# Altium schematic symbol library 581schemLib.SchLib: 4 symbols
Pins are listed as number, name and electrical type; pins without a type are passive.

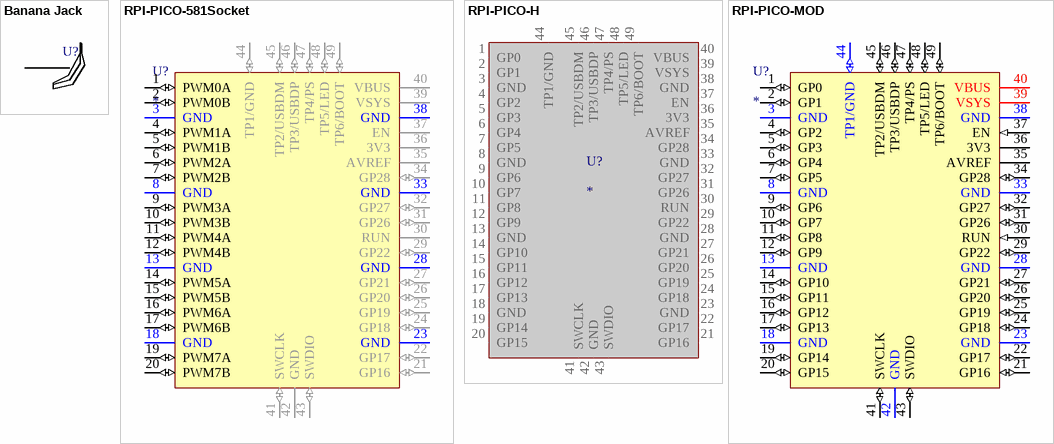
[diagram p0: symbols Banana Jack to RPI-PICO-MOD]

## Banana Jack
designator U?  (value not drawn)
575-8
footprint Banana Jack (575-8)
pins: 1

## RPI-PICO-581Socket
designator U?
RASPBERRY PI PICO RP2040 BOARD; Manufacturer: Raspberry Pi Foundation; Manufacturer Part No: SC0915
footprint RPI-PICO-MOD (RASPBERRY PI PICO RP2040 BOARD)
pins: 1 PWM0A (io), 2 PWM0B (io), 3 GND (power), 4 PWM1A (io), 5 PWM1B (io), 6 PWM2A (io), 7 PWM2B (io), 8 GND (power), 9 PWM3A (io), 10 PWM3B (io), 11 PWM4A (io), 12 PWM4B (io), 13 GND (power), 14 PWM5A (io), 15 PWM5B (io), 16 PWM6A (io), 17 PWM6B (io), 18 GND (power), 19 PWM7A (io), 20 PWM7B (io), 21 GP16 (io), 22 GP17 (io), 23 GND (power), 24 GP18 (io), 25 GP19 (io), 26 GP20 (io), 27 GP21 (io), 28 GND (power), 29 GP22 (io), 30 RUN (hiz), 31 GP26 (io), 32 GP27 (io), 33 GND (power), 34 GP28 (io), 35 AVREF (power), 36 3V3 (power), 37 EN (hiz), 38 GND (power), 39 VSYS (power), 40 VBUS (power), 41 SWCLK (io), 42 GND (power), 43 SWDIO (io), 44 TP1/GND (io), 45 TP2/USBDM (io), 46 TP3/USBDP (io), 47 TP4/PS (io), 48 TP5/LED (io), 49 TP6/BOOT (io)

## RPI-PICO-H
designator U?
RASPBERRY PI PICO HRP2040 BOARD; Manufacturer: Raspberry Pi Foundation; Manufacturer Part No: SC0915
pins: 1 GP0 (hiz), 2 GP1 (hiz), 3 GND (hiz), 4 GP2 (hiz), 5 GP3 (hiz), 6 GP4 (hiz), 7 GP5 (hiz), 8 GND (hiz), 9 GP6 (hiz), 10 GP7 (hiz), 11 GP8 (hiz), 12 GP9 (hiz), 13 GND (hiz), 14 GP10 (hiz), 15 GP11 (hiz), 16 GP12 (hiz), 17 GP13 (hiz), 18 GND (hiz), 19 GP14 (hiz), 20 GP15 (hiz), 21 GP16 (hiz), 22 GP17 (hiz), 23 GND (hiz), 24 GP18 (hiz), 25 GP19 (hiz), 26 GP20 (hiz), 27 GP21 (hiz), 28 GND (hiz), 29 GP22 (hiz), 30 RUN (hiz), 31 GP26 (hiz), 32 GP27 (hiz), 33 GND (hiz), 34 GP28 (hiz), 35 AVREF (hiz), 36 3V3 (hiz), 37 EN (hiz), 38 GND (hiz), 39 VSYS (hiz), 40 VBUS (hiz), 41 SWCLK (hiz), 42 GND (hiz), 43 SWDIO (hiz), 44 TP1/GND (hiz), 45 TP2/USBDM (hiz), 46 TP3/USBDP (hiz), 47 TP4/PS (hiz), 48 TP5/LED (hiz), 49 TP6/BOOT (hiz)

## RPI-PICO-MOD
designator U?
RASPBERRY PI PICO RP2040 BOARD; Manufacturer: Raspberry Pi Foundation; Manufacturer Part No: SC0915
footprint RPI-PICO-MOD (RASPBERRY PI PICO RP2040 BOARD)
pins: 1 GP0 (io), 2 GP1 (io), 3 GND (power), 4 GP2 (io), 5 GP3 (io), 6 GP4 (io), 7 GP5 (io), 8 GND (power), 9 GP6 (io), 10 GP7 (io), 11 GP8 (io), 12 GP9 (io), 13 GND (power), 14 GP10 (io), 15 GP11 (io), 16 GP12 (io), 17 GP13 (io), 18 GND (power), 19 GP14 (io), 20 GP15 (io), 21 GP16 (io), 22 GP17 (io), 23 GND (power), 24 GP18 (io), 25 GP19 (io), 26 GP20 (io), 27 GP21 (io), 28 GND (power), 29 GP22 (io), 30 RUN (in), 31 GP26 (io), 32 GP27 (io), 33 GND (power), 34 GP28 (io), 35 AVREF (power), 36 3V3 (power), 37 EN (in), 38 GND (power), 39 VSYS (power), 40 VBUS (power), 41 SWCLK (io), 42 GND (power), 43 SWDIO (io), 44 TP1/GND (io), 45 TP2/USBDM (io), 46 TP3/USBDP (io), 47 TP4/PS (io), 48 TP5/LED (io), 49 TP6/BOOT (io)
